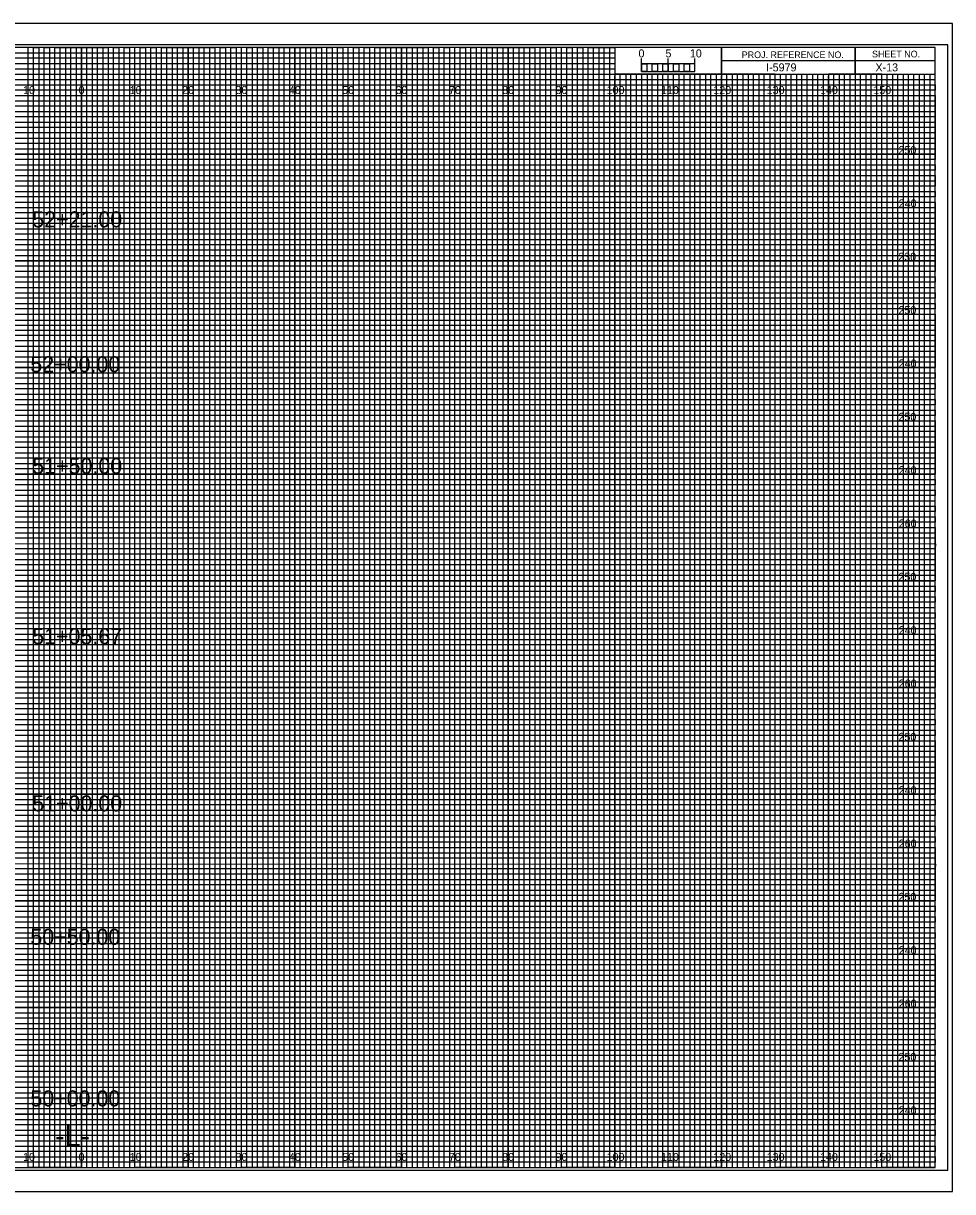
# Model space of a CAD drawing. Extents: x -13 to 359, y -5 to 2854.
# Drawn here: x 149.1 to 323.3, y 2635.5 to 2854.5 of the extents above; entities that cross this region are included whole.
import ezdxf

# ---------------------------------------------------------------- set-up
doc = ezdxf.new("R2010")
doc.units = 0
for name, color, linetype in [('Exist CMT Pavement', 7, 'Continuous'), ('Exist Cross Section Cell', 7, 'Continuous'), ('Exist XS Ground Line', 7, 'Continuous'), ('Prop CMT Conc Surface', 7, 'Continuous'), ('Prop CMT Concrete Structures', 7, 'Continuous'), ('Prop CMT DNC', 7, 'Continuous'), ('Prop CMT Pvmt Course 1', 7, 'Continuous'), ('Prop CMT Pvmt Course 1 CG', 7, 'Continuous'), ('Prop CMT Pvmt Course 1 Wedge', 7, 'Continuous'), ('Prop CMT Pvmt Course 2', 7, 'Continuous'), ('Prop CMT Pvmt Course 2 Wedge', 7, 'Continuous'), ('Prop CMT Pvmt Course 3', 7, 'Continuous'), ('Prop CMT Pvmt Course 3 Wedge', 7, 'Continuous'), ('Prop CMT Shear Line', 7, 'Continuous'), ('Prop CMT Slope Grass', 7, 'Continuous'), ('Prop CMT Subgrade Earthwork', 7, 'Continuous'), ('Scratch_Level_0', 7, 'Continuous')]:
    doc.layers.add(name, color=color, linetype=linetype)

msp = doc.modelspace()

# ---------------------------------------------------------------- linework, layer by layer
at = {"layer": 'Exist XS Ground Line'}
for p, q in [((150, 2850), (140, 2850)), ((150, 2640), (150, 2850)), ((170, 2850), (160, 2850)), ((160, 2850), (160, 2640)), ((170, 2640), (170, 2850)), ((190, 2850), (180, 2850)), ((180, 2850), (180, 2640)), ((190, 2640), (190, 2850)), ((210, 2850), (200, 2850)), ((200, 2850), (200, 2640)), ((210, 2640), (210, 2850)), ((230, 2850), (220, 2850)), ((220, 2850), (220, 2640)), ((230, 2640), (230, 2850)), ((250, 2850), (240, 2850)), ((240, 2850), (240, 2640)), ((250, 2640), (250, 2850)), ((260, 2850), (260, 2640)), ((270, 2640), (270, 2845)), ((290, 2845), (280, 2845)), ((280, 2845), (280, 2640)), ((290, 2640), (290, 2845)), ((310, 2845), (300, 2845)), ((300, 2845), (300, 2640)), ((310, 2640), (310, 2845)), ((160, 2640), (150, 2640)), ((180, 2640), (170, 2640)), ((200, 2640), (190, 2640)), ((220, 2640), (210, 2640)), ((240, 2640), (230, 2640)), ((260, 2640), (250, 2640)), ((280, 2640), (270, 2640)), ((300, 2640), (290, 2640)), ((320, 2640), (310, 2640)), ((320, 2640), (320, 2640))]:
    msp.add_line(p, q, dxfattribs=at)
for points in [[(0, 2840), (320, 2840), (320, 2830), (0, 2830)], [(0, 2820), (320, 2820), (320, 2810), (0, 2810)], [(0, 2800), (320, 2800), (320, 2790), (0, 2790)], [(0, 2780), (320, 2780), (320, 2770), (0, 2770)], [(0, 2760), (320, 2760), (320, 2750), (0, 2750)], [(0, 2740), (320, 2740), (320, 2730), (0, 2730)], [(0, 2720), (320, 2720), (320, 2710), (0, 2710)], [(0, 2700), (320, 2700), (320, 2690), (0, 2690)], [(0, 2680), (320, 2680), (320, 2670), (0, 2670)], [(0, 2660), (320, 2660), (320, 2650), (0, 2650)]]:
    msp.add_lwpolyline(points, dxfattribs=at)
at = {"layer": 'Prop CMT Conc Surface'}
for p, q in [((265, 2845.49), (265, 2847.9)), ((265, 2846.9), (265, 2847.9)), ((270, 2845.49), (270, 2847.9)), ((275, 2845.49), (275, 2847.9)), ((275, 2846.9), (275, 2847.9))]:
    msp.add_line(p, q, dxfattribs=at)
for points in [[(275, 2846.9), (265, 2846.9), (265, 2845.49), (275, 2845.49)], [(265, 2846.9), (266, 2846.9), (266, 2845.49), (265, 2845.49)], [(267, 2846.9), (268, 2846.9), (268, 2845.49), (267, 2845.49)], [(269, 2846.9), (270, 2846.9), (270, 2845.49), (269, 2845.49)], [(271, 2846.9), (272, 2846.9), (272, 2845.49), (271, 2845.49)], [(273, 2846.9), (274, 2846.9), (274, 2845.49), (273, 2845.49)]]:
    msp.add_lwpolyline(points, close=True, dxfattribs=at)
at = {"layer": 'Prop CMT Concrete Structures'}
for p, q in [((305, 2850), (305, 2845)), ((305, 2845), (305, 2850)), ((280, 2847.5), (280, 2845)), ((320, 2847.49), (280, 2847.49)), ((280, 2845), (320, 2845))]:
    msp.add_line(p, q, dxfattribs=at)
for points in [[(320, 2850), (0, 2850), (0, 2640), (320, 2640)], [(280, 2850), (260, 2850), (260, 2845.03), (280, 2845.03)], [(320, 2850), (280, 2850), (280, 2845), (320, 2845)]]:
    msp.add_lwpolyline(points, close=True, dxfattribs=at)
at = {"layer": 'Prop CMT DNC'}
for p, q in [((323.3, 2854.5), (-13.4, 2854.5)), ((-13.4, 2635.5), (323.3, 2635.5))]:
    msp.add_line(p, q, dxfattribs=at)
at = {"layer": 'Prop CMT Pvmt Course 1'}
for p, q in [((0, 2849), (260, 2849)), ((260, 2847.98), (0, 2847.98)), ((0, 2847), (260, 2847)), ((260, 2849), (260, 2847.98)), ((260, 2847), (260, 2845.89)), ((260, 2845.89), (0, 2845.89)), ((0, 2844), (320, 2844))]:
    msp.add_line(p, q, dxfattribs=at)
for points in [[(0, 2843), (270, 2843), (320, 2843), (320, 2842), (0, 2842)], [(0, 2841), (320, 2841), (320, 2839), (0, 2839)], [(0, 2838), (320, 2838), (320, 2837), (0, 2836.98)], [(0, 2836), (320, 2836), (320, 2834), (0, 2834)], [(0, 2833), (320, 2833), (320, 2832), (0, 2832)], [(0, 2831), (320, 2831), (320, 2829), (0, 2829)], [(0, 2828), (320, 2828), (320, 2827), (0, 2827)], [(0, 2826), (320, 2826), (320, 2824), (0, 2824)], [(0, 2823), (320, 2823), (320, 2822), (0, 2822)], [(0, 2821), (320, 2821), (320, 2819), (0, 2819)], [(0, 2818), (320, 2818), (320, 2817), (0, 2817)], [(0, 2816), (320, 2816), (320, 2813.95), (320, 2813), (320, 2812), (0, 2812)], [(0, 2814), (320, 2814), (320, 2813), (0, 2813)], [(0, 2811), (320, 2811), (320, 2809), (0, 2809.03)], [(0, 2809.03), (320, 2809), (320, 2808), (0, 2808)], [(0, 2807), (320, 2807), (320, 2806), (0, 2806)], [(0, 2804), (320, 2804), (320, 2803), (0, 2803)], [(0, 2802), (320, 2802), (320, 2801), (0, 2801)], [(-0.07, 2798.89), (320, 2798.89), (320, 2797.88), (-0.07, 2797.88)], [(0, 2797), (320, 2797), (320, 2796), (0, 2796)], [(0, 2794), (320, 2794), (320, 2793), (0, 2793)], [(0, 2792), (320, 2792), (320, 2791), (0, 2791)], [(0, 2789), (320, 2789), (320, 2788), (0, 2788)], [(0, 2787), (320, 2787), (320, 2786), (0, 2786)], [(0, 2784), (320, 2784), (320, 2783), (0, 2783)], [(0, 2782), (320, 2782), (320, 2781), (0, 2781)], [(0, 2779), (320, 2779), (319.99, 2777.98), (0, 2778)], [(0, 2777), (320, 2777), (320, 2776), (0, 2776)], [(0, 2774), (320, 2774), (320, 2773), (0, 2773)], [(0, 2772), (320, 2772), (320, 2771), (0, 2771)], [(0, 2769), (320, 2769), (320, 2768), (0, 2768)], [(0, 2767), (320, 2767), (320, 2766), (0, 2766)], [(0, 2764), (320, 2764), (320, 2763), (0, 2763)], [(0, 2762), (320, 2762), (320, 2761), (0, 2761)], [(0, 2759), (320, 2759), (320, 2758), (0, 2758)], [(0, 2756.99), (320.07, 2756.91), (320, 2756), (0, 2756)], [(0, 2754), (320, 2754), (320, 2753), (0, 2753)], [(0, 2752), (320, 2752), (320, 2751), (0, 2751)], [(0, 2749), (320, 2749), (320, 2748), (0, 2748)], [(0, 2747), (320, 2747), (320, 2746), (0, 2746)], [(0, 2744), (320, 2744), (320, 2743), (0, 2743)], [(0, 2742), (320, 2742), (320, 2741), (0, 2741)], [(0, 2739), (320, 2739), (320, 2738), (0, 2738)], [(0, 2737), (320, 2737), (320, 2736), (0, 2736)], [(0, 2734), (320, 2734), (320, 2733), (0, 2733)], [(0, 2732), (320, 2732), (320, 2731), (0, 2731)], [(0, 2729), (320, 2729), (320, 2728), (0, 2728)], [(0, 2727), (320, 2727), (320, 2726), (0, 2726)], [(0, 2724), (320, 2724), (320, 2723), (0, 2723)], [(0, 2722), (320, 2722), (320, 2721), (0, 2721)], [(0, 2719), (320, 2719), (319.99, 2717.98), (0, 2718)], [(0, 2717), (320, 2717), (320, 2716), (0, 2716)], [(0, 2714), (320, 2714), (320, 2713), (0, 2713)], [(0, 2712), (320, 2712), (320, 2711), (0, 2711)], [(0, 2709), (320, 2709), (320, 2708), (0, 2708)], [(0, 2707), (320, 2707), (320, 2706), (0, 2706)], [(0, 2704), (320, 2704), (320, 2703), (0, 2703)], [(0, 2702), (320, 2702), (320, 2701), (0, 2701)], [(0, 2699), (320, 2699), (320, 2698), (0, 2698)], [(0, 2696.99), (320.07, 2696.91), (320, 2696), (0, 2696)], [(0, 2694), (320, 2694), (320, 2693), (0, 2693)], [(0, 2692), (320, 2692), (320, 2691), (0, 2691)], [(0, 2689), (320, 2689), (320, 2688), (0, 2688)], [(0, 2687), (320, 2687), (320, 2686), (0, 2686)], [(0, 2684), (320, 2684), (320, 2683), (0, 2683)], [(0, 2682), (320, 2682), (320, 2681), (0, 2681)], [(0, 2679), (320, 2679), (320, 2678), (0, 2678)], [(0, 2677), (320, 2677), (320, 2676), (0, 2676)], [(0, 2674), (320, 2674), (320, 2673), (0, 2673)], [(0, 2672), (320, 2672), (320, 2671), (0, 2671)], [(0, 2669), (320, 2669), (320, 2668), (0, 2668)], [(0, 2667), (320, 2667), (320, 2666), (0, 2666)], [(0, 2664), (320, 2664), (320, 2663), (0, 2663)], [(0, 2662), (320, 2662), (320, 2661), (0, 2661)], [(0, 2659), (320, 2659), (320, 2658), (0, 2658)], [(0, 2657), (320, 2657), (320, 2656), (0, 2656)], [(0, 2654), (320, 2654), (320, 2653), (0, 2653)], [(0, 2652), (320, 2652), (320, 2651), (0, 2651)], [(0, 2649), (320, 2649), (320, 2648), (0, 2648)], [(0, 2647), (320, 2647), (320, 2646), (0, 2646)], [(0, 2644), (320, 2644), (320, 2643), (0, 2643)], [(0, 2642), (320, 2642), (320, 2641), (0, 2641)]]:
    msp.add_lwpolyline(points, dxfattribs=at)
at = {"layer": 'Prop CMT Pvmt Course 1 CG'}
for p, q in [((267, 2845), (266.01, 2845)), ((266.01, 2845), (266.01, 2640)), ((267, 2640), (267, 2845)), ((269, 2845), (268, 2845)), ((268, 2845), (268, 2640)), ((269, 2640), (269, 2845)), ((266.01, 2640), (265, 2640)), ((268, 2640), (267, 2640))]:
    msp.add_line(p, q, dxfattribs=at)
for points in [[(150, 2640), (151, 2640), (151, 2850), (152, 2850), (152, 2640)], [(152, 2640), (153, 2640), (153, 2850), (154, 2850), (154, 2640)], [(155, 2640), (156, 2640), (156, 2850), (157, 2850), (157, 2640)], [(157, 2640), (158, 2640), (158, 2850), (159, 2850), (159, 2640)], [(160, 2640), (161, 2640), (161, 2850), (162, 2850), (162, 2640)], [(162, 2640), (163, 2640), (163, 2850), (164, 2850), (164, 2640)], [(165, 2640), (166, 2640), (166, 2850), (167, 2850), (167, 2640)], [(167, 2640), (168, 2640), (168, 2850), (169, 2850), (169, 2640)], [(170, 2640), (171, 2640), (171, 2850), (172, 2850), (172, 2640)], [(172, 2640), (173, 2640), (173, 2850), (174, 2850), (174, 2640)], [(175, 2640), (176, 2640), (176, 2850), (177, 2850), (177, 2640)], [(177, 2640), (178, 2640), (178, 2850), (179, 2850), (179, 2640)], [(180, 2640), (181, 2640), (181, 2850), (182, 2850), (182, 2640)], [(182, 2640), (183, 2640), (183, 2850), (184, 2850), (184, 2640)], [(185, 2640), (186, 2640), (186, 2850), (187, 2850), (187, 2640)], [(187, 2640), (188, 2640), (188, 2850), (189, 2850), (189, 2640)], [(190, 2640), (191, 2640), (191, 2850), (192, 2850), (192, 2640)], [(192, 2640), (193, 2640), (193, 2850), (194, 2850), (194, 2640)], [(195, 2640), (196, 2640), (196, 2850), (197, 2850), (197, 2640)], [(197, 2640), (198, 2640), (198, 2850), (199, 2850), (199, 2640)], [(200, 2640), (201, 2640), (201, 2850), (202, 2850), (202, 2640)], [(202, 2640), (203, 2640), (203, 2850), (204, 2850), (204, 2640)], [(205, 2640), (206, 2640), (206, 2850), (207, 2850), (207, 2640)], [(207, 2640), (208, 2640), (208, 2850), (209, 2850), (209, 2640)], [(210, 2640), (211, 2640), (211, 2850), (212, 2850), (212, 2640)], [(212, 2640), (213, 2640), (213, 2850), (214, 2850), (214, 2640)], [(215, 2640), (216, 2640), (216, 2850), (217, 2850), (217, 2640)], [(217, 2640), (218, 2640), (218, 2850), (219, 2850), (219, 2640)], [(220, 2640), (221, 2640), (221, 2850), (222, 2850), (222, 2640)], [(222, 2640), (223, 2640), (223, 2850), (224, 2850), (224, 2640)], [(225, 2640), (226, 2640), (226, 2850), (227, 2850), (227, 2640)], [(227, 2640), (228, 2640), (228, 2850), (229, 2850), (229, 2640)], [(230, 2640), (231, 2640), (231, 2850), (232, 2850), (232, 2640)], [(232, 2640), (233, 2640), (233, 2850), (234, 2850), (234, 2640)], [(235, 2640), (236, 2640), (236, 2850), (237, 2850), (237, 2640)], [(237, 2640), (238, 2640), (238, 2850), (239, 2850), (239, 2640)], [(240, 2640), (241, 2640), (241, 2850), (242, 2850), (242, 2640)], [(242, 2640), (243, 2640), (243, 2850), (244, 2850), (244, 2640)], [(245, 2640), (246, 2640), (246, 2850), (247, 2850), (247, 2640)], [(247, 2640), (248, 2640), (248, 2850), (249, 2850), (249, 2640)], [(250, 2640), (251, 2640), (251, 2850), (252, 2850), (252, 2640)], [(252, 2640), (253, 2640), (253, 2850), (254, 2850), (254, 2640)], [(255, 2640), (256, 2640), (256, 2850), (257, 2850), (257, 2640)], [(257, 2640), (258, 2640), (258, 2850), (259, 2850), (259, 2640)], [(260, 2640), (261, 2640), (261, 2845), (262.02, 2845), (262.02, 2640)], [(262, 2640), (263, 2640), (263, 2845), (263.99, 2845), (263.99, 2640)], [(270, 2640), (270.98, 2640), (270.98, 2845), (272, 2845), (272, 2640)], [(272, 2640), (273, 2640), (273, 2845), (274.05, 2845), (274.05, 2640)], [(275, 2640), (276, 2640), (276, 2845), (277, 2845), (277, 2640)], [(277, 2640), (278, 2640), (278, 2845), (279, 2845), (279, 2640)], [(280, 2640), (281, 2640), (281, 2845), (282, 2845), (282, 2640)], [(282, 2640), (283, 2640), (283, 2845), (284, 2845), (284, 2640)], [(285, 2640), (286, 2640), (286, 2845), (287, 2845), (287, 2640)], [(287, 2640), (288, 2640), (288, 2845), (289, 2845), (289, 2640)], [(290, 2640), (291, 2640), (291, 2845), (292, 2845), (292, 2640)], [(292, 2640), (293, 2640), (293, 2845), (294, 2845), (294, 2640)], [(295, 2640), (296, 2640), (296, 2845), (297, 2845), (297, 2640)], [(297, 2640), (298, 2640), (298, 2845), (299, 2845), (299, 2640)], [(300, 2640), (301, 2640), (301, 2845), (302, 2845), (302, 2640)], [(302, 2640), (303, 2640), (303, 2845), (304, 2845), (304, 2640)], [(305, 2640), (306, 2640), (306, 2845), (307, 2845), (307, 2640)], [(307, 2640), (308, 2640), (308, 2845), (309, 2845), (309, 2640)], [(310, 2640), (311, 2640), (311, 2845), (312, 2845), (312, 2640)], [(312, 2640), (313, 2640), (313, 2845), (314, 2845), (314, 2640)], [(315, 2640), (316, 2640), (316, 2845), (317, 2845), (317, 2640)], [(317, 2640), (318, 2640), (318, 2845), (319, 2845), (319, 2640)]]:
    msp.add_lwpolyline(points, dxfattribs=at)
at = {"layer": 'Prop CMT Shear Line'}
for p, q in [((150, 2640), (150, 2850)), ((160, 2640), (160, 2850)), ((170, 2640), (170, 2850)), ((180, 2640), (180, 2850)), ((190, 2640), (190, 2850)), ((200, 2640), (200, 2850)), ((210, 2640), (210, 2850)), ((220, 2640), (220, 2850)), ((230, 2640), (230, 2850)), ((240, 2640), (240, 2850)), ((250, 2640), (250, 2850)), ((260, 2640), (260, 2844.69)), ((270, 2640), (270, 2844.69)), ((280, 2640), (280, 2844.69)), ((290, 2640), (290, 2844.69)), ((300, 2640), (300, 2844.69)), ((310, 2640), (310, 2844.69)), ((0, 2840), (320, 2840)), ((0, 2830), (320, 2830)), ((0, 2820), (320, 2820)), ((0, 2810), (320, 2810)), ((0, 2800), (320, 2800)), ((0, 2790), (320, 2790)), ((0, 2780), (320, 2780)), ((0, 2770), (320, 2770)), ((0, 2760), (320, 2760)), ((0, 2750), (320, 2750)), ((0, 2740), (320, 2740)), ((0, 2730), (320, 2730)), ((0, 2720), (320, 2720)), ((0, 2710), (320, 2710)), ((0, 2700), (320, 2700)), ((0, 2690), (320, 2690)), ((0, 2680), (320, 2680)), ((0, 2670), (320, 2670)), ((0, 2660), (320, 2660)), ((0, 2650), (320, 2650))]:
    msp.add_line(p, q, dxfattribs=at)
at = {"layer": 'Prop CMT Slope Grass'}
msp.add_lwpolyline([(-10.8, 2639.5), (322.4, 2639.5), (322.4, 2850.5), (-10.8, 2850.5)], close=True, dxfattribs=at)
at = {"layer": 'Prop CMT Subgrade Earthwork'}
msp.add_lwpolyline([(-13.4, 2635.5), (323.3, 2635.5), (323.3, 2854.5), (-13.4, 2854.5)], close=True, dxfattribs=at)
at = {"layer": 'Scratch_Level_0'}
for points in [[(145, 2640), (155, 2640), (155, 2850), (165, 2850), (165, 2640), (175, 2640), (175, 2850), (185, 2850), (185, 2640), (195, 2640), (195, 2850), (205, 2850), (205, 2640), (215, 2640), (215, 2850), (225, 2850), (225, 2640), (235, 2640), (235, 2850), (245, 2850), (245, 2640), (255, 2640), (255, 2850), (259.93, 2850), (260, 2850), (260, 2845), (264.99, 2845), (264.99, 2640), (275, 2640), (275, 2845), (285, 2845), (285, 2640), (295, 2640), (295, 2845), (305, 2845), (305, 2640), (315, 2640), (315, 2845)], [(0, 2845), (275, 2845)], [(0, 2825), (320, 2825), (320, 2835), (0, 2835)], [(0, 2805), (320, 2805), (320, 2815), (0, 2815)], [(0, 2785), (320, 2785), (320, 2795), (0, 2795)], [(0, 2765), (320, 2765), (320, 2775), (0, 2775)], [(0, 2745), (320, 2745), (320, 2755), (0, 2755)], [(0, 2725), (320, 2725), (320, 2735), (0, 2735)], [(0, 2705), (320, 2705), (320, 2715), (0, 2715)], [(0, 2685), (320, 2685), (320, 2695), (0, 2695)], [(0, 2665), (320, 2665), (320, 2675), (0, 2675)], [(0, 2645), (320, 2645), (320, 2655), (0, 2655)]]:
    msp.add_lwpolyline(points, dxfattribs=at)

# ---------------------------------------------------------------- texts
at = {"layer": 'Exist CMT Pavement'}
for s, p in [('5', (269.47, 2848.12)), ('10', (274.04, 2848.12))]:
    msp.add_text(s, height=1.5, dxfattribs=at).set_placement(p)
at = {"layer": 'Exist Cross Section Cell'}
for s, p in [('10', (149.04, 2841.25)), ('0', (159.45, 2841.25)), ('0', (159.45, 2841.25)), ('10', (169.04, 2841.25)), ('20', (178.86, 2841.25)), ('30', (188.86, 2841.25)), ('40', (198.86, 2841.25)), ('50', (208.86, 2841.25)), ('60', (218.86, 2841.25)), ('70', (228.86, 2841.25)), ('80', (238.86, 2841.25)), ('90', (248.86, 2841.25)), ('100', (258.44, 2841.25)), ('110', (268.62, 2841.25)), ('120', (278.44, 2841.25)), ('130', (288.44, 2841.25)), ('140', (298.44, 2841.25)), ('150', (308.44, 2841.25)), ('10', (149.04, 2641.25)), ('0', (159.45, 2641.25)), ('0', (159.45, 2641.25)), ('10', (169.04, 2641.25)), ('20', (178.86, 2641.25)), ('30', (188.86, 2641.25)), ('40', (198.86, 2641.25)), ('50', (208.86, 2641.25)), ('60', (218.86, 2641.25)), ('70', (228.86, 2641.25)), ('80', (238.86, 2641.25)), ('90', (248.86, 2641.25)), ('100', (258.44, 2641.25)), ('110', (268.62, 2641.25)), ('120', (278.44, 2641.25)), ('130', (288.44, 2641.25)), ('140', (298.44, 2641.25)), ('150', (308.44, 2641.25))]:
    msp.add_text(s, height=1.5, dxfattribs=at).set_placement(p)
at = {"layer": 'Prop CMT Conc Surface'}
msp.add_text('0', height=1.5, dxfattribs=at).set_placement((264.41, 2848.12))
at = {"layer": 'Prop CMT Concrete Structures'}
for s, p in [('PROJ. REFERENCE NO.', (283.77, 2847.99)), ('SHEET NO.', (308.19, 2848.12))]:
    msp.add_text(s, height=1.25, dxfattribs=at).set_placement(p)
at = {"layer": 'Prop CMT Pvmt Course 1 Wedge'}
msp.add_text('X-13', height=1.5, dxfattribs=at).set_placement((308.83, 2845.5))
at = {"layer": 'Prop CMT Pvmt Course 2'}
for s, p in [('250', (313.15, 2830)), ('240', (313.19, 2820)), ('230', (313.11, 2810)), ('250', (313.15, 2800)), ('240', (313.19, 2790)), ('250', (313.15, 2780)), ('240', (313.19, 2770)), ('260', (313.19, 2760)), ('250', (313.15, 2750)), ('240', (313.19, 2740)), ('260', (313.19, 2730)), ('250', (313.15, 2720)), ('240', (313.19, 2710)), ('260', (313.19, 2700)), ('250', (313.15, 2690)), ('240', (313.19, 2680)), ('260', (313.19, 2670)), ('250', (313.15, 2660)), ('240', (313.19, 2650))]:
    msp.add_text(s, height=1.5, dxfattribs=at).set_placement(p)
at = {"layer": 'Prop CMT Pvmt Course 2 Wedge'}
msp.add_text('I-5979', height=1.5, dxfattribs=at).set_placement((288.34, 2845.5))
at = {"layer": 'Prop CMT Pvmt Course 3'}
for s, p in [('52+21.00', (150.77, 2816.26)), ('52+00.00', (150.41, 2789.1)), ('51+50.00', (150.77, 2770.05)), ('51+05.67', (150.76, 2738.12)), ('51+00.00', (150.77, 2706.78)), ('50+50.00', (150.41, 2681.77)), ('50+00.00', (150.41, 2651.48))]:
    msp.add_text(s, height=3, dxfattribs=at).set_placement(p)
at = {"layer": 'Prop CMT Pvmt Course 3 Wedge'}
msp.add_text('-L-', height=4, dxfattribs=at).set_placement((155.06, 2644))

doc.saveas('drawing.dxf')
